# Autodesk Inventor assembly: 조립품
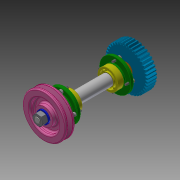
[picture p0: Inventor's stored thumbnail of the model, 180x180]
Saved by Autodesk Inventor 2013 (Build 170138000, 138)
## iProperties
Created: 2019-11
Part Number: 조립품
Document SubType Name: Assembly
Designer: Administrator
Author: Administrator
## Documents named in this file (14)
- C:\Users\Administrator\Desktop\491104V1019\조립품.iam
- C:\Users\Administrator\Desktop\491104V1019\본체.ipt
- C:\Users\Administrator\Desktop\491104V1019\축.ipt
- C:\Users\Administrator\Desktop\491104V1019\커버.ipt
- C:\Users\Administrator\Desktop\491104V1019\키 5x5x12.ipt
- C:\Users\Administrator\Desktop\491104V1019\V-벨트풀리.ipt
- V-벨트풀리.ipt
- C:\Users\Administrator\Desktop\491104V1019\너트 M12x1.25.ipt
- C:\Users\Administrator\Desktop\491104V1019\베어링 6203.ipt
- C:\Users\Administrator\Desktop\491104V1019\볼트 M4.ipt
- C:\Users\Administrator\Desktop\491104V1019\부시.ipt
- C:\Users\Administrator\Desktop\491104V1019\스퍼기어.ipt
- C:\Users\Administrator\Desktop\491104V1019\오일 실 26 38 8.ipt
- C:\Users\Administrator\Desktop\491104V1019\와셔 12x24.ipt
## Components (1 placed, 1 different names)
1. V-벨트풀리:1
